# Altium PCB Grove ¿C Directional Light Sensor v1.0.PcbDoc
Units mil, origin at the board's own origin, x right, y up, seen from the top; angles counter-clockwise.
Board outline 952.76 x 787.4 mil, 2 copper layers (Top, Bottom); 14 components, 9 nets, 33 pads, 7 vias.
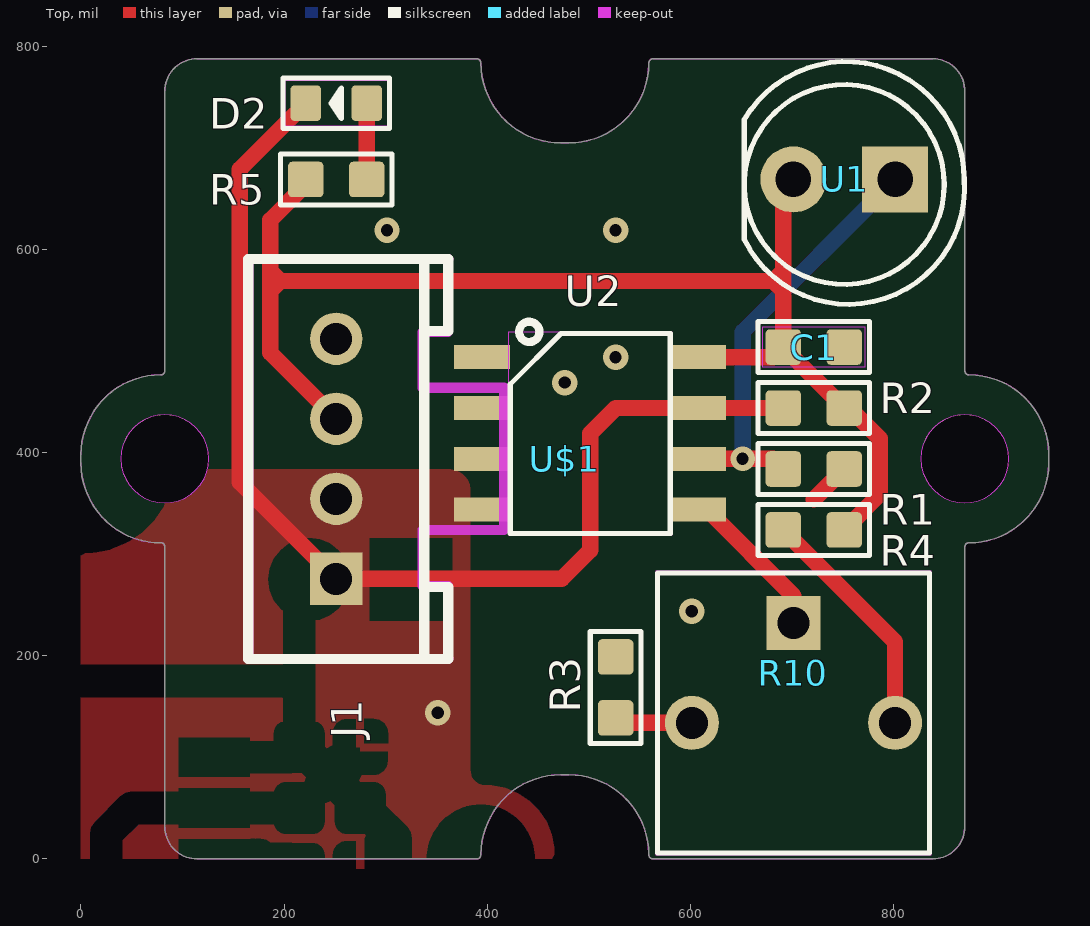
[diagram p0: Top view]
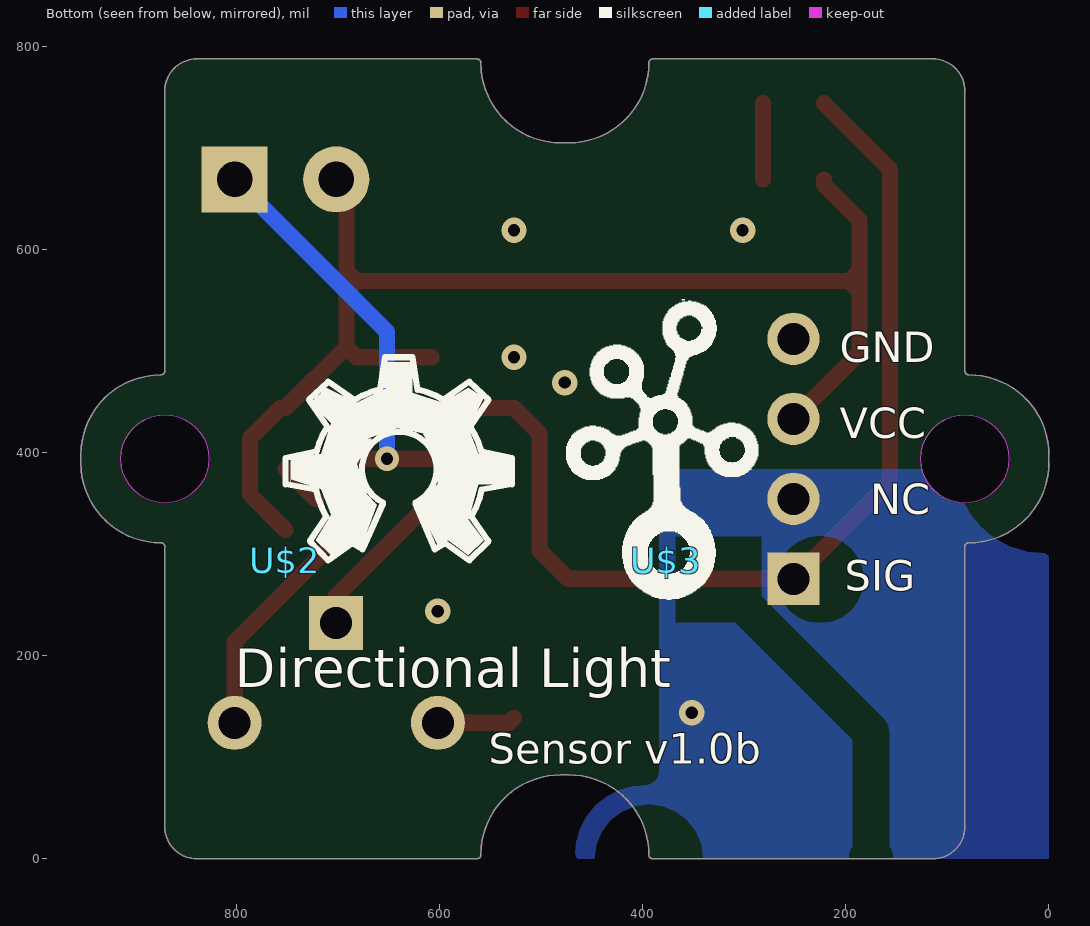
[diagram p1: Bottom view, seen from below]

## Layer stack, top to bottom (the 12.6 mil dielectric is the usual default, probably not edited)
Top Solder: solder mask 0.4, Solder Resist, Dk 3.5
Top: signal copper 1.378
Dielectric 1: dielectric 12.6, FR-4, Dk 4.8
Bottom: signal copper 1.378
Bottom Solder: solder mask 0.4, Solder Resist, Dk 3.5

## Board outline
114.18,787.4 389.77,787.4 cw(c389.76,783.47) 393.7,783.46 ccw(c472.44,783.46) 472.44,704.72 480.32,704.72 ccw(c480.32,783.46) 559.06,783.46 cw(c563,783.47) 562.99,787.4 838.58,787.4 cw(c838.58,755.9) 870.08,755.9 870.08,480.31 ccw(c874.01,480.31) 874.02,476.38 cw(c874.02,397.64) 952.76,397.64 952.76,389.76 cw(c874.02,389.76) 874.02,311.02 ccw(c874.01,307.08) 870.08,307.09 870.08,31.5 cw(c838.58,31.5) 838.58,0 562.99,0 cw(c563,3.94) 559.06,3.94 ccw(c480.32,3.94) 480.32,82.68 472.44,82.68 ccw(c472.44,3.94) 393.7,3.94 cw(c389.76,3.94) 389.77,0 114.18,0 cw(c114.18,31.5) 82.68,31.5 82.68,307.09 ccw(c78.75,307.08) 78.74,311.02 cw(c78.74,389.76) 0,389.76 0,397.64 cw(c78.74,397.64) 78.74,476.38 ccw(c78.75,480.31) 82.68,480.31 82.68,755.9 cw(c114.18,755.9)
cut-out: 82.68,350.39 ccw(c82.68,393.7) 125.98,393.7 ccw(c82.68,393.7) 82.68,437 ccw(c82.68,393.7) 39.38,393.7 ccw(c82.68,393.7)
cut-out: 870.08,350.39 ccw(c870.08,393.7) 913.38,393.7 ccw(c870.08,393.7) 870.08,437 ccw(c870.08,393.7) 826.77,393.7 ccw(c870.08,393.7)

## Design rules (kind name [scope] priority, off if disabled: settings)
BoardOutlineClearance mdCopperDimension [All] p1: gap=10 ignorepadtopadclearanceinfootprint=FALSE except(0: Arc-SplitContinuation Track-SplitContinuation SMDPad-SplitContinuation THPad-SplitContinuation Via-SplitContinuation Fill-SplitContinuation Poly-SplitContinuation Region-SplitContinuation Text-SplitContinuation)
Clearance Clearance_for_PolygonClass_Isolate_8 [InPolygonClass('Isolate_8') vs IsArc Or IsTrack Or IsPad Or IsVia Or IsFill Or IsRegion Or IsText] p1: gap=8 ignorepadtopadclearanceinfootprint=FALSE
Clearance Clearance_for_PolygonClass_Isolate_10 [InPolygonClass('Isolate_10') vs IsArc Or IsTrack Or IsPad Or IsVia Or IsFill Or IsRegion Or IsText] p2: gap=10 ignorepadtopadclearanceinfootprint=FALSE
Clearance "Clearance (Same Net)" [All] p3: gap=6 ignorepadtopadclearanceinfootprint=FALSE
Clearance [All] p4: gap=6 ignorepadtopadclearanceinfootprint=FALSE
HoleSize [All] p1: absolutevalues=TRUE maxlimit=100000 minlimit=12 maxpercent=80.000 minpercent=20.000
HoleToHoleClearance mdDrill [All] p1: gap=10 allowstackedmicrovias=TRUE
MinimumSolderMaskSliver [All] p1 off: minsoldermaskwidth=10
PasteMaskExpansion mlMinCreamFrame [All] p1: expansion=0
PolygonConnect PolygonConnect_For_PolygonThermal_ON_Width80000_Gap100000 [InPolygonClass('PolygonThermal_ON_Width80000_Gap100000') vs Not IsVia] p1: connectstyle=Relief reliefconductorwidth=8 reliefentries=4 polygonreliefangle="90 Angle" airgapwidth=10
PolygonConnect ThermalVias [IsVia] p2: connectstyle=Direct reliefconductorwidth=10 reliefentries=4 polygonreliefangle="90 Angle" airgapwidth=10
PolygonConnect [All] p3: connectstyle=Relief reliefconductorwidth=10 reliefentries=4 polygonreliefangle="90 Angle" airgapwidth=10
RoutingVias [All] p1: holewidth=12 width=24 viastyle="Through Hole" minholewidth=12 minwidth=24 maxholewidth=100 maxwidth=100
SolderMaskExpansion mlMinStopFrame [All] p1: expansion=2
Width [All] p1: maxlimit=10000 minlimit=6 preferedwidth=6
26 further rules are at their usual default settings.

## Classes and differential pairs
polygon class PolygonThermal_ON_Width80000_Gap100000: Polygon_1_Net_GND Polygon_2_Net_GND
polygon class Isolate_8: Polygon_1_Net_GND
polygon class Isolate_10: Polygon_2_Net_GND

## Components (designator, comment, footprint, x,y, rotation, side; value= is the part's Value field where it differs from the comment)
C1 "100nF" C0603 721.38,503.7 r0 top
D2 "Green" LED-0603 251.38,743.7 r180 top
J1 "Grove-4P" 4P-2.0 251.38,393.7 r90 top
R1 "10K" R0603 721.38,383.7 r180 top
R2 "3K" R0603 721.38,443.7 r180 top
R3 "100" R0603 526.38,168.7 r270 top
R4 "100" R0603 721.38,323.7 r0 top
R5 "1K" R0603 251.38,668.7 r180 top
R10 "1K" 3P-SQUA-7X6.8 701.38,143.7 r0 top
U1 "YG1006" 2P-2.54-5MM 751.38,668.7 r180 top
U2 "" SOIC8-6.0 501.38,418.7 r270 top
U$1 "" 1U-DIM-W/-DRILL 476.38,393.7 r90 top
U$2 "" OSHW_FILLX200_NOTEXT 751.38,293.7 r180 bottom
U$3 "" TWIGLOGO 376.38,293.7 r180 bottom

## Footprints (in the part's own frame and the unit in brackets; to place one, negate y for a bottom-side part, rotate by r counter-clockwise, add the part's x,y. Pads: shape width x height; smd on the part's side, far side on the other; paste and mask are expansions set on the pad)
1U-DIM-W/-DRILL [mil] "1U-DIM-W/-DRILL"
2P-2.54-5MM [mil] "2P-2.54-5MM"
  rect 65x65 / inner rect 60x60 / far side rect 65x65 hole 35: 1(-50,0)
  round 65 / inner round 60 / far side round 65 hole 35: 2(50,0)
  silkscreen extent -118,-116 98,123
3P-SQUA-7X6.8 [mm] "3P-SQUA-7X6.8"
  round 1.35 / inner round 1.524 / far side round 1.35 hole 0.8: 1(-2.54,-0.25) 2(2.54,-0.25)
  rect 1.35x1.35 / inner rect 1.524x1.524 / far side rect 1.35x1.35 hole 0.8: 3(0,2.25)
  Top keep-out region: -3.429,-3.556 -3.429,3.556 3.429,3.556 3.429,-3.556
  silkscreen extent -3.4,-3.5 3.4,3.5
4P-2.0 [mil] "4P-2.0"
  rect 51.5x51.5 / inner rect 60x60 / far side rect 51.5x51.5 hole 31.5: 1(-118.11,0)
  round 51.5 / inner round 60 / far side round 51.5 hole 31.5: 2(-39.37,0) 3(39.37,0) 4(118.11,0)
  Top keep-out lines w10: -195,-110 -125,-110 -125,-85 -70,-85 -70,-165 70,-165 70,-85 125,-85 125,-110 195,-110 ; -196.85,-110.24 -196.85,86.61 196.85,86.61 196.85,-110.24
  silkscreen extent -197,-110 197,87
C0603 [mil] "C0603"
  rrect25% 35x35 smd: 1(-30,0) 2(30,0)
  Top keep-out region: -50,-20 -50,20 50,20 50,-20
  silkscreen extent -55,-25 55,25
LED-0603 [mil] "LED-0603"
  rrect25% 30x35 smd: +(-30,0) -(30,0)
  Top keep-out region: -50,-22.5 -50,22.5 50,22.5 50,-22.5
  silkscreen extent -52,-25 52,25
OSHW_FILLX200_NOTEXT [mil] "OSHW_FILLX200_NOTEXT"
  silkscreen extent 0,0 223,200
R0603 [mil] "R0603"
  rrect25% 35x35 smd: 1(-30,0) 2(30,0)
  silkscreen extent -55,-25 55,25
SOIC8-6.0 [mm] "SOIC8-6.0"
  rect 0.6x1.4 smd: 1(-1.905,-2.7) 2(-0.635,-2.7) 3(0.635,-2.7) 4(1.905,-2.7) 5(1.905,2.7) 6(0.635,2.7) 7(-0.635,2.7) 8(-1.905,2.7)
  Top keep-out region: -2.54,-2.032 -2.54,2.032 2.54,2.032 2.54,-2.032
  silkscreen extent -2.79,-2 2.5,2
TWIGLOGO [mil] "TWIGLOGO"
  silkscreen extent -98,-38 91,257

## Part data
C1: library part C0603
D2: library part LED-0603
J1: library part 4P-2.0
R1 R2 R3 R4 R5: library part R0603
R10: library part 3P-SQUA-7X6.8
U1: library part 2P-2.54-5MM
U2: library part SOIC8-6.0
U$1: library part 1U-DIM-W/-DRILL
U$2: library part OSHW_FILLX200_NOTEXT
U$3: library part TWIGLOGO

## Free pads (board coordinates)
  round 86.61 hole 86.61 unplated: MH1(870.08,393.7) MH2(82.68,393.7)

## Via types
v1: diameter 25/25 (per signal layer), hole 12, Top to Bottom, tented both sides, 6 vias
v2: diameter 24/24 (per signal layer), hole 12, Top to Bottom, tented both sides, 1 vias

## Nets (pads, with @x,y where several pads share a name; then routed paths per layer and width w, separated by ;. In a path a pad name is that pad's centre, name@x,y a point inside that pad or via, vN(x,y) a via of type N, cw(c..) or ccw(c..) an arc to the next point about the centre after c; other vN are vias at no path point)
GND: C1.2 J1.4 R1.1 R3.1 U2.2 U2.3 U2.4 | length 42.4
  Top w16: 721.38,353.7 R1.1
  other v1: 351.38,143.7 601.38,243.7 476.38,468.7 526.38,493.7 301.38,618.7 526.38,618.7
N$1: R1.2 U1.1 U2.6 | length 425
  Top w16: U2.6 v2(651.38,393.7) 681.38,393.7 R1.2
  Bottom w16: v2(651.38,393.7) 651.38,518.7 U1.1
N$2: D2.+ R5.1 | length 75
  Top w16: R5.1 D2.+
N$3: R3.2 R10.1 | length 77
  Top w16: R3.2 531.22,133.86 R10.1
N$4: R4.1 R10.2 | length 235.4
  Top w16: R4.1 801.38,213.7 R10.2
N$5: R10.3 U2.5 | length 155.3
  Top w16: U2.5 616.38,343.7 701.38,258.7 R10.3
NC: J1.2
SIG: D2.- J1.1 R2.2 U2.7 | length 1111.4
  Top w16: D2.- 156.38,678.7 156.38,370.59 J1.1 473.27,275.59 501.38,303.7 501.38,418.7 526.38,443.7 U2.7 R2.2
VCC: C1.1 J1.3 R2.1 R4.2 R5.2 U1.2 U2.8 | length 1334.5
  Top w16: R5.2 221.38,663.7 186.38,628.7 186.38,578.7 ; J1.3 186.38,498.07 186.38,558.7 ; U2.8 681.38,493.7 C1.1 ; U1.2 691.38,658.7 691.38,578.7 ; R4.2 786.38,358.7 786.38,413.7 756.38,443.7 R2.1 C1.1 ; 186.38,558.7 196.38,568.7 ; 186.38,558.7 186.38,568.7 ; 186.38,568.7 196.38,568.7 ; 186.38,568.7 186.38,578.7 ; 186.38,578.7 196.38,568.7 ; 196.38,568.7 681.38,568.7 ; 681.38,568.7 691.38,558.7 ; 681.38,568.7 691.38,578.7 ; 681.38,568.7 686.38,568.7 691.38,573.7 ; C1.1 691.38,558.7 ; 691.38,558.7 691.38,573.7 ; 691.38,573.7 691.38,578.7
pads on no net: U2.1

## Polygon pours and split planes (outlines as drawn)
GND on Top "Polygon_1_Net_GND" (solid, remove dead copper, pour order 1): -27.62,-10.3 980.38,-10.3 980.38,797.7 -27.62,797.7 -27.62,-1.3
GND on Bottom "Polygon_2_Net_GND" (solid, remove dead copper, pour order 0): -27.62,-10.3 980.38,-10.3 980.38,797.7 -27.62,797.7 -27.62,-1.3

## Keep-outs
Keep-Out Layer:
  the board outline again, w0

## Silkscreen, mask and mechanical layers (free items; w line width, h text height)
Bottom Overlay:
  text "GND" at 205.69,488.96 h29.75
  text "VCC" at 205.69,413.96 h29.75
  text "NC" at 175.95,338.96 h29.75
  text "SIG" at 200.73,263.96 h29.75
  text "Directional Light" at 801.38,168.7 h38.25
  text "Sensor v1.0b" at 551.38,93.7 h29.75
Dimension:
  the board outline again, w0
